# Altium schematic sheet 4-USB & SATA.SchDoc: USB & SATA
size B; CompanyName: NGRF; Address1: 2130 Howard Drive W; Address2: North Mankato, MN 56003; Address3: www.nextgenrf.com; Revision: 2; SheetNumber: 4; SheetTotal: 7; ProjName: BytePipe X9002_HDK
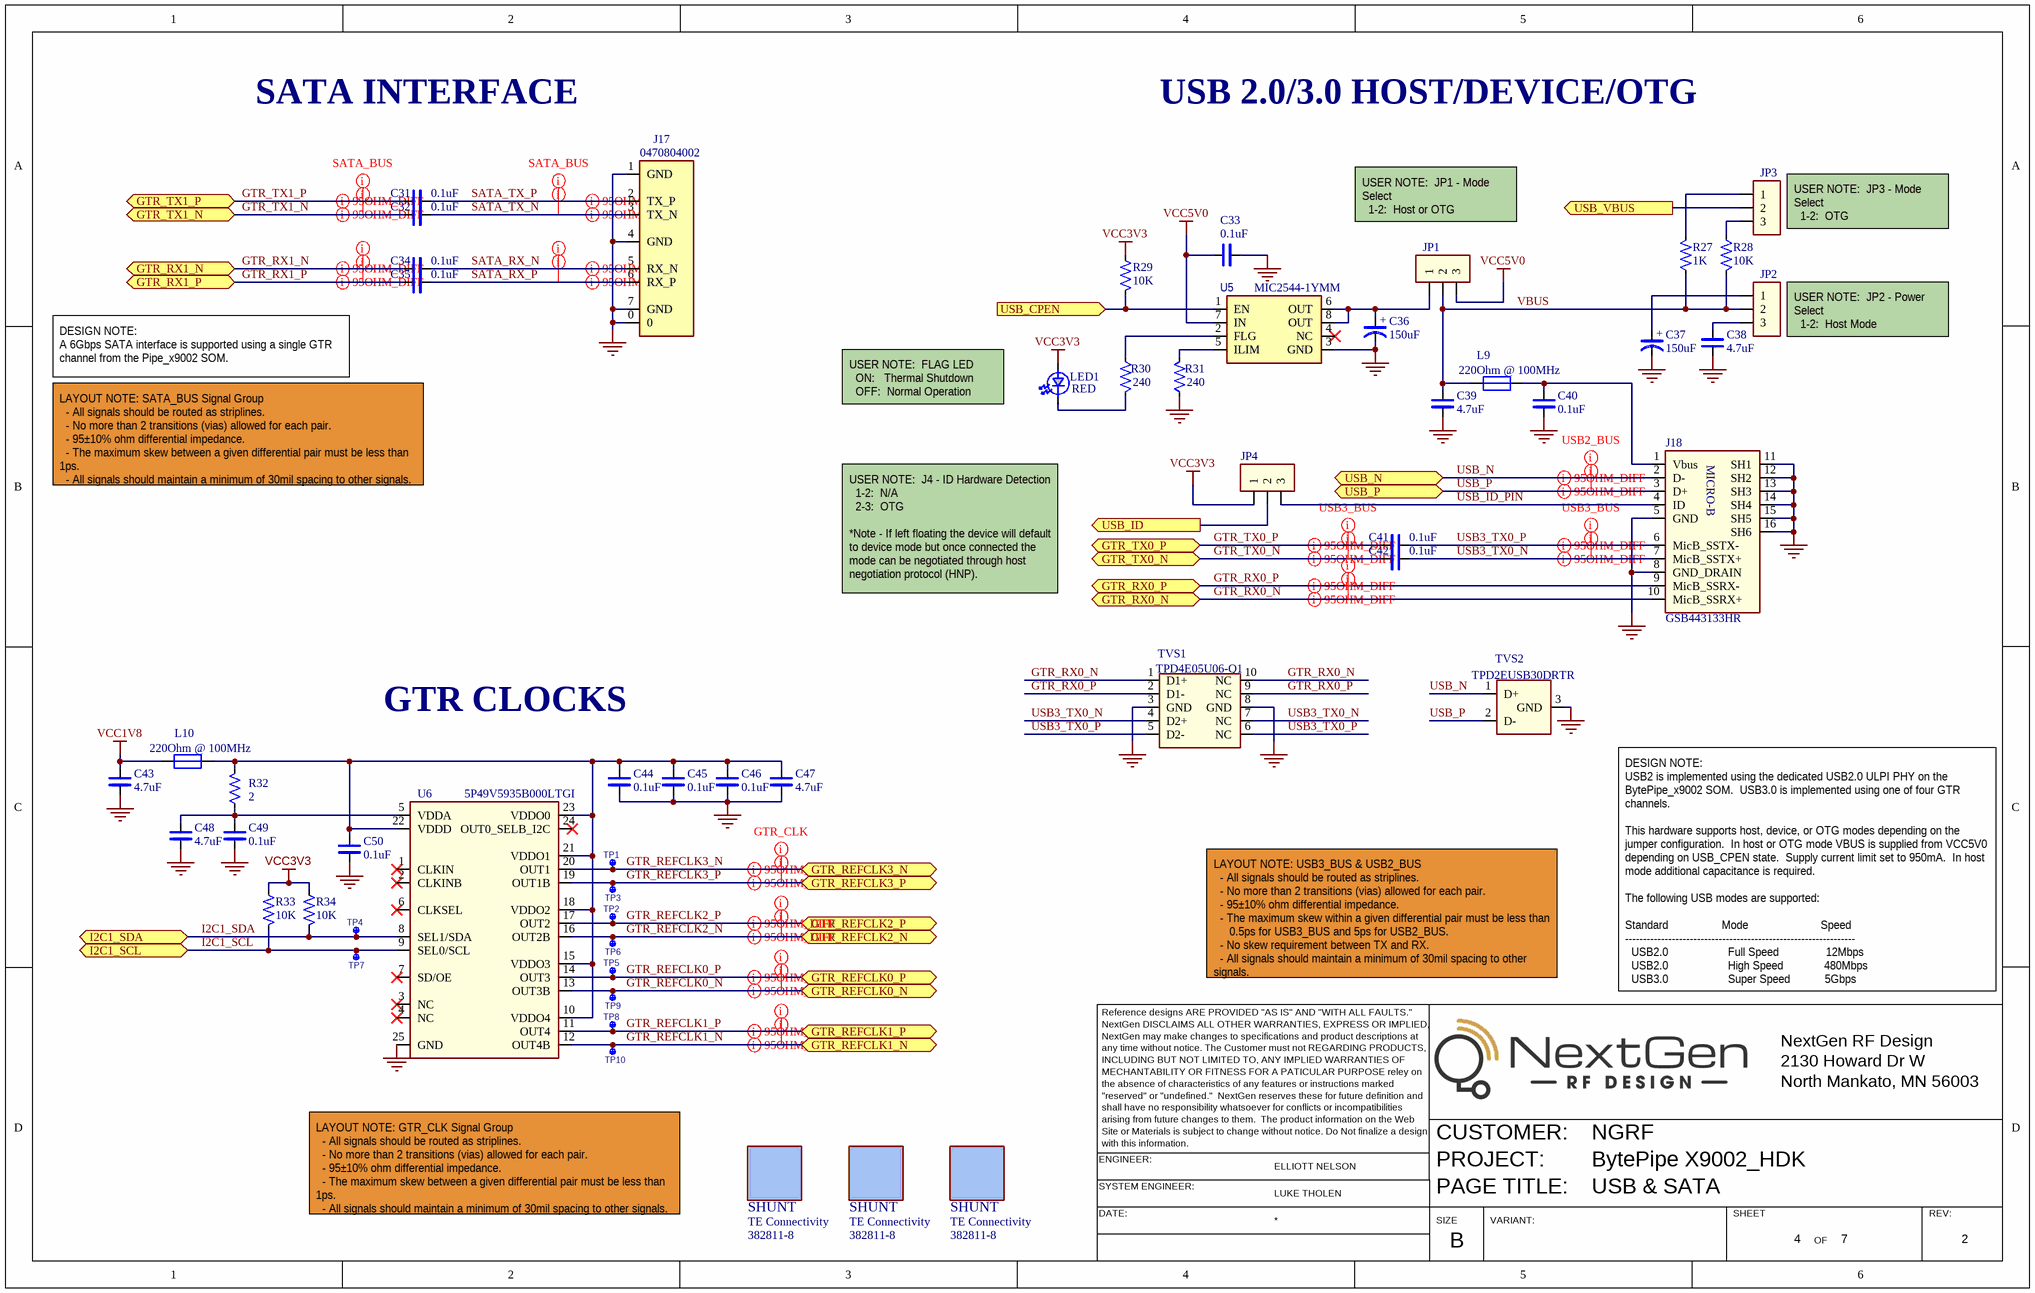
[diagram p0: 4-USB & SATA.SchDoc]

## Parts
C31  value 0.1uF  [SM/0402/CAP]  (hidden comment: CAP_CERAMIC_0402)
C32  value 0.1uF  [SM/0402/CAP]  (hidden comment: CAP_CERAMIC_0402)
C33  value 0.1uF  [SM/0402/CAP]  (hidden comment: CAP_CERAMIC_0402)
C34  value 0.1uF  [SM/0402/CAP]  (hidden comment: CAP_CERAMIC_0402)
C35  value 0.1uF  [SM/0402/CAP]  (hidden comment: CAP_CERAMIC_0402)
C36  value 150uF  [SM/CAP/TANT-D_A]  (hidden comment: TANT-D)
C37  value 150uF  [SM/CAP/TANT-D_A]  (hidden comment: TANT-D)
C38  value 4.7uF  [SM/0402/CAP]  (hidden comment: CAP_CERAMIC_0402)
C39  value 4.7uF  [SM/0402/CAP]  (hidden comment: CAP_CERAMIC_0402)
C40  value 0.1uF  [SM/0402/CAP]  (hidden comment: CAP_CERAMIC_0402)
C41  value 0.1uF  [SM/0402/CAP]  (hidden comment: CAP_CERAMIC_0402)
C42  value 0.1uF  [SM/0402/CAP]  (hidden comment: CAP_CERAMIC_0402)
C43  value 4.7uF  [SM/0402/CAP]  (hidden comment: CAP_CERAMIC_0402)
C44  value 0.1uF  [SM/0402/CAP]  (hidden comment: CAP_CERAMIC_0402)
C45  value 0.1uF  [SM/0402/CAP]  (hidden comment: CAP_CERAMIC_0402)
C46  value 0.1uF  [SM/0402/CAP]  (hidden comment: CAP_CERAMIC_0402)
C47  value 4.7uF  [SM/0402/CAP]  (hidden comment: CAP_CERAMIC_0402)
C48  value 4.7uF  [SM/0402/CAP]  (hidden comment: CAP_CERAMIC_0402)
C49  value 0.1uF  [SM/0402/CAP]  (hidden comment: CAP_CERAMIC_0402)
C50  value 0.1uF  [SM/0402/CAP]  (hidden comment: CAP_CERAMIC_0402)
J17  value 0470804002  [SM/CON/MLX/SATA/0470804002]  (hidden comment: CON_MOLEX_0470804002)
J18  value GSB443133HR  [SM/CON/USB3.1/MICRO B]  (hidden comment: CON_USB_3.1_MICRO-B_RA)
JP1  CON_100SP_1X3P_038H  [CON/100SP/1X3P]  (value not drawn)
JP2  CON_100SP_1X3P_038H  [CON/100SP/1X3P]  (value not drawn)
JP3  CON_100SP_1X3P_038H  [CON/100SP/1X3P]  (value not drawn)
JP4  CON_100SP_1X3P_038H  [CON/100SP/1X3P]  (value not drawn)
L9  value 220Ohm @ 100MHz  [SM/0603]  (hidden comment: FERRITE_0603_A)
L10  value 220Ohm @ 100MHz  [SM/0603]  (hidden comment: FERRITE_0603_A)
LED1  value RED  [SM/LED_0603]  (hidden comment: LED_0603)
R27  value 1K  [SM/0402/RES]  (hidden comment: RES_0402_A)
R28  value 10K  [SM/0402/RES]  (hidden comment: RES_0402_A)
R29  value 10K  [SM/0402/RES]  (hidden comment: RES_0402_A)
R30  value 240  [SM/0402/RES]  (hidden comment: RES_0402_A)
R31  value 240  [SM/0402/RES]  (hidden comment: RES_0402_A)
R32  value 2  [SM/0402/RES]  (hidden comment: RES_0402_A)
R33  value 10K  [SM/0402/RES]  (hidden comment: RES_0402_A)
R34  value 10K  [SM/0402/RES]  (hidden comment: RES_0402_A)
S1  SHUNT  OEM NAME: TE Connectivity  OEM#: 382811-8
S2  SHUNT  OEM NAME: TE Connectivity  OEM#: 382811-8
S3  SHUNT  OEM NAME: TE Connectivity  OEM#: 382811-8
TP1  TESTPOINT_030  [SM/TESTPOINT/30MIL]  (value not drawn)  (no BOM)
TP2  TESTPOINT_030  [SM/TESTPOINT/30MIL]  (value not drawn)  (no BOM)
TP3  TESTPOINT_030  [SM/TESTPOINT/30MIL]  (value not drawn)  (no BOM)
TP4  TESTPOINT_030  [SM/TESTPOINT/30MIL]  (value not drawn)  (no BOM)
TP5  TESTPOINT_030  [SM/TESTPOINT/30MIL]  (value not drawn)  (no BOM)
TP6  TESTPOINT_030  [SM/TESTPOINT/30MIL]  (value not drawn)  (no BOM)
TP7  TESTPOINT_030  [SM/TESTPOINT/30MIL]  (value not drawn)  (no BOM)
TP8  TESTPOINT_030  [SM/TESTPOINT/30MIL]  (value not drawn)  (no BOM)
TP9  TESTPOINT_030  [SM/TESTPOINT/30MIL]  (value not drawn)  (no BOM)
TP10  TESTPOINT_030  [SM/TESTPOINT/30MIL]  (value not drawn)  (no BOM)
TVS1  value TPD4E05U06-Q1  [SM/DFN10/2.5X1MM_A]  (hidden comment: TVS_TPD4E05U06_2.5mmX1mm)
TVS2  value TPD2EUSB30DRTR  [SM/SOT3_A]  (hidden comment: TVS_TPD2EUSB30DRTR_SOT3)
U5  value MIC2544-1YMM  [SM/MSOP8_A]  (hidden comment: IC_MIC2544-1YMM_MSOP-8)
U6  value 5P49V5935B000LTGI  [SM/LGA24/4X4/0.5LS_A]  (hidden comment: IC_5P49V5935_LGA-24)

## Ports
GTR_REFCLK0_N (bidir), GTR_REFCLK0_P (bidir), GTR_REFCLK1_N (bidir), GTR_REFCLK1_P (bidir), GTR_REFCLK2_N (bidir), GTR_REFCLK2_P (bidir), GTR_REFCLK3_N (bidir), GTR_REFCLK3_P (bidir), GTR_RX0_N (bidir), GTR_RX0_P (bidir), GTR_RX1_N (bidir), GTR_RX1_P (bidir), GTR_TX0_N (bidir), GTR_TX0_P (bidir), GTR_TX1_N (bidir), GTR_TX1_P (bidir), I2C1_SCL (bidir), I2C1_SDA (bidir), USB_CPEN (in), USB_ID (out), USB_N (bidir), USB_P (bidir), USB_VBUS (out)

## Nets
GND: C33.2(N2) C36.2(N) C37.2(N) C38.2(N2) C39.2(N2) C40.2(N2) C43.2(N2) C44.2(N2) C45.2(N2) C46.2(N2) C47.2(N2) C48.2(N2) C49.2(N2) C50.2(N2) J17.0 J17.1(GND) J17.4(GND) J17.7(GND) J18.5(GND) J18.8(GND_DRAIN) J18.11(SH1) J18.12(SH2) J18.13(SH3) J18.14(SH4) J18.15(SH5) J18.16(SH6) R31.2 TVS1.3(GND) TVS1.8(GND) TVS2.3(GND) U5.3(GND) U6.25(GND)
VCC1V8: C43.1(N1) L10.1(PIN1)
VCC3V3: JP4.1 LED1.2(A) R29.1 R33.1 R34.1
VCC5V0: C33.1(N1) JP1.3 U5.7(IN)
GTR_REFCLK0_N: TP9.1(N1) U6.13(OUT3B) ; port GTR_REFCLK0_N
GTR_REFCLK0_P: TP5.1(N1) U6.14(OUT3) ; port GTR_REFCLK0_P
GTR_REFCLK1_N: TP10.1(N1) U6.12(OUT4B) ; port GTR_REFCLK1_N
GTR_REFCLK1_P: TP8.1(N1) U6.11(OUT4) ; port GTR_REFCLK1_P
GTR_REFCLK2_N: TP6.1(N1) U6.16(OUT2B) ; port GTR_REFCLK2_N
GTR_REFCLK2_P: TP2.1(N1) U6.17(OUT2) ; port GTR_REFCLK2_P
GTR_REFCLK3_N: TP1.1(N1) U6.20(OUT1) ; port GTR_REFCLK3_N
GTR_REFCLK3_P: TP3.1(N1) U6.19(OUT1B) ; port GTR_REFCLK3_P
GTR_RX0_N: J18.10(MicB_SSRX+) TVS1.1(D1+) TVS1.10(NC) ; port GTR_RX0_N
GTR_RX0_P: J18.9(MicB_SSRX-) TVS1.2(D1-) TVS1.9(NC) ; port GTR_RX0_P
GTR_RX1_N: C34.1(N1) ; port GTR_RX1_N
GTR_RX1_P: C35.1(N1) ; port GTR_RX1_P
GTR_TX0_N: C42.1(N1) ; port GTR_TX0_N
GTR_TX0_P: C41.1(N1) ; port GTR_TX0_P
GTR_TX1_N: C32.1(N1) ; port GTR_TX1_N
GTR_TX1_P: C31.1(N1) ; port GTR_TX1_P
I2C1_SCL: R33.2 TP7.1(N1) U6.9(SEL0/SCL) ; port I2C1_SCL
I2C1_SDA: R34.2 TP4.1(N1) U6.8(SEL1/SDA) ; port I2C1_SDA
SATA_RX_N: C34.2(N2) J17.5(RX_N)
SATA_RX_P: C35.2(N2) J17.6(RX_P)
SATA_TX_N: C32.2(N2) J17.3(TX_N)
SATA_TX_P: C31.2(N2) J17.2(TX_P)
USB3_TX0_N: C42.2(N2) J18.7(MicB_SSTX+) TVS1.4(D2+) TVS1.7(NC)
USB3_TX0_P: C41.2(N2) J18.6(MicB_SSTX-) TVS1.5(D2-) TVS1.6(NC)
USB_CPEN: R29.2 U5.1(EN) ; port USB_CPEN
USB_ID: JP4.2 ; port USB_ID
USB_ID_PIN: J18.4(ID) JP4.3
USB_N: J18.2(D-) TVS2.1(D+) ; port USB_N
USB_P: J18.3(D+) TVS2.2(D-) ; port USB_P
USB_VBUS: JP3.2 ; port USB_VBUS
VBUS: C39.1(N1) JP1.2 JP2.2 L9.1(PIN1) R27.1 R28.2
NetC36_1: C36.1(+) JP1.1 U5.6(OUT) U5.8(OUT)
NetC37_1: C37.1(+) JP2.1
NetC38_1: C38.1(N1) JP2.3
NetC40_1: C40.1(N1) J18.1(Vbus) L9.2(PIN2)
NetC44_1: C44.1(N1) C45.1(N1) C46.1(N1) C47.1(N1) C50.1(N1) L10.2(PIN2) R32.1 U6.10(VDDO4) U6.15(VDDO3) U6.18(VDDO2) U6.21(VDDO1) U6.22(VDDD) U6.23(VDDO0)
NetC48_1: C48.1(N1) C49.1(N1) R32.2 U6.5(VDDA)
NetJP3_1: JP3.1 R27.2
NetJP3_3: JP3.3 R28.1
NetLED1_1: LED1.1(C) R30.1
NetR30_2: R30.2 U5.2(FLG)
NetR31_1: R31.1 U5.5(ILIM)

Not connected (* = marked no-connect by the designer): U5 4(NC)*; U6 1(CLKIN)* 2(CLKINB)* 3(NC)* 4(NC)* 6(CLKSEL)* 7(SD/OE)* 24(OUT0_SELB_I2C)*

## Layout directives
net class USB3_BUS: GTR_RX0_N, GTR_RX0_P, GTR_TX0_N, GTR_TX0_P, USB3_TX0_N, USB3_TX0_P
net class USB2_BUS: USB_N, USB_P
differential pair; Impedance: 90 Ohms; differential pair class 95OHM_DIFF: GTR_REFCLK0_N, GTR_REFCLK0_P, GTR_REFCLK1_N, GTR_REFCLK1_P, GTR_REFCLK2_N, GTR_REFCLK2_P, GTR_REFCLK3_N, GTR_REFCLK3_P, GTR_RX0_N, GTR_RX0_P, GTR_RX1_N, GTR_RX1_P, GTR_TX0_N, GTR_TX0_P, GTR_TX1_N, GTR_TX1_P, SATA_RX_N, SATA_RX_P, SATA_TX_N, SATA_TX_P, USB3_TX0_N, USB3_TX0_P, USB_N, USB_P
net class SATA_BUS: GTR_RX1_N, GTR_RX1_P, GTR_TX1_N, GTR_TX1_P, SATA_RX_N, SATA_RX_P, SATA_TX_N, SATA_TX_P
net class GTR_CLK: GTR_REFCLK0_N, GTR_REFCLK0_P, GTR_REFCLK1_N, GTR_REFCLK1_P, GTR_REFCLK2_N, GTR_REFCLK2_P, GTR_REFCLK3_N, GTR_REFCLK3_P

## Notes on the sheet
- SATA INTERFACE
- USB 2.0/3.0 HOST/DEVICE/OTG
- USER NOTE:  JP1 - Mode Select
  1-2:  Host or OTG
  2-3:  Device
- (near JP3) USER NOTE:  JP3 - Mode Select
  1-2:  OTG
  2-3:  Device or Host
- DESIGN NOTE:
  A 6Gbps SATA interface is supported using a single GTR channel from the Pipe_x9002 SOM.
- (near JP2) USER NOTE:  JP2 - Power Select
  1-2:  Host Mode
  2-3:  Device or OTG
- USER NOTE:  FLAG LED
  ON:   Thermal Shutdown
  OFF:  Normal Operation
- LAYOUT NOTE: SATA_BUS Signal Group
  - All signals should be routed as striplines.
  - No more than 2 transitions (vias) allowed for each pair.
  - 95±10% ohm differential impedance.
  - The maximum skew between a given differential pair must be less than 1ps.
  - All signals should maintain a minimum of 30mil spacing to other signals.
- USER NOTE:  J4 - ID Hardware Detection
  1-2:  N/A
  2-3:  OTG
  *Note - If left floating the device will default to device mode but once connected the mode can be negotiated through host negotiation protocol (HNP).
- GTR CLOCKS
- LAYOUT NOTE: USB3_BUS & USB2_BUS
  - All signals should be routed as striplines.
  - No more than 2 transitions (vias) allowed for each pair.
  - 95±10% ohm differential impedance.
  - The maximum skew within a given differential pair must be less than
  0.5ps for USB3_BUS and 5ps for USB2_BUS.
  - No skew requirement between TX and RX.
  - All signals should maintain a minimum of 30mil spacing to other signals.
- Reference designs ARE PROVIDED "AS IS" AND "WITH ALL FAULTS."
- NextGen DISCLAIMS ALL OTHER WARRANTIES, EXPRESS OR IMPLIED,
- NextGen may make changes to specifications and product descriptions at
- DESIGN NOTE:
  USB2 is implemented using the dedicated USB2.0 ULPI PHY on the BytePipe_x9002 SOM.  USB3.0 is implemented using one of four GTR channels.
  This hardware supports host, device, or OTG modes depending on the jumper configuration.  In host or OTG mode VBUS is supplied from VCC5V0 depending on USB_CPEN state.  Supply current limit set to 950mA.  In host mode additional capacitance is required.
  The following USB modes are supported:
  Standard                 Mode                       Speed
  ----------------------------------------------------------------
  USB2.0                   Full Speed               12Mbps
  USB2.0                   High Speed             480Mbps
  USB3.0                   Super Speed           5Gbps
- NextGen RF Design
- any time without notice. The Customer must not REGARDING PRODUCTS,
- INCLUDING BUT NOT LIMITED TO, ANY IMPLIED WARRANTIES OF
- MECHANTABILITY OR FITNESS FOR A PATICULAR PURPOSE reley on
- "reserved" or "undefined."  NextGen reserves these for future definition and
- the absence of characteristics of any features or instructions marked
- shall have no responsibility whatsoever for conflicts or incompatibilities
- 2130 Howard Dr W
- North Mankato, MN 56003
- ENGINEER:
- Site or Materials is subject to change without notice. Do Not finalize a design
- with this information.
- arising from future changes to them.  The product information on the Web
- ELLIOTT NELSON
- CUSTOMER:
- PROJECT:
- LAYOUT NOTE: GTR_CLK Signal Group
  - All signals should be routed as striplines.
  - No more than 2 transitions (vias) allowed for each pair.
  - 95±10% ohm differential impedance.
  - The maximum skew between a given differential pair must be less than 1ps.
  - All signals should maintain a minimum of 30mil spacing to other signals.
- SYSTEM ENGINEER:
- DATE:
- LUKE THOLEN
- SIZE
- PAGE TITLE:
- VARIANT:
- SHEET
- OF
- REV:
- B

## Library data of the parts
C31-C35 C40-C42 C44-C46 C49 C50 = CAP_CERAMIC_0402: CAP CER 0.1UF 25V X7R 0402; TOL: ±10%; OEM#: CL05B104KA5NNNC; OEM NAME: Samsung
C36 C37 = CAP_TANT-D: CAP TANT 150UF 20% 10V 2917; OEM#: T491D157M010AT; OEM NAME: KEMET
C38 C39 C43 C47 C48 = CAP_CERAMIC_0402: CAP CER 4.7UF 10V X5R 0402; TOL: ±20%; OEM#: CL05A475MP5NRNC; OEM NAME: Samsung
J17 = CON_MOLEX_0470804002: 7 Position SATA Plug Connector Solder Surface Mount, Right Angle; OEM NAME: MOLEX
J18 = CON_USB_3.1_MICRO-B_RA: CONN RCPT USB3.1 MICRO B SMD R/A; OEM NAME: Amphenol ICC
JP1-JP4 = CON_100SP_1X3P_038H: PIN HEADER, SINGLE ROW 3 PIN STR; OEM#: PH1-03-UA; OEM NAME: Adam Tech; VALUE: PH1-03-UA
L9 L10 = FERRITE_0603_A: 120 Ohms @ 100MHz 1 Power Line Ferrite Bead 0603 (1608 Metric) 3A 25mOhm; OEM#: BLM18SG121TN1D; OEM NAME: Murata Electronics
LED1 = LED_0603: LED-0603; OEM#: LS Q976-NR-1; OEM NAME: OSRAM
R27 = RES_0402_A: RES SMD 1K OHM 1% 1/10W 0402; OEM#: ERJ-2RKF1001X; OEM NAME: Panasonic
R28 R29 R33 R34 = RES_0402_A: OEM#: ERJ-2RKF1002X; OEM NAME: Panasonic; TOL: ±1%
R30 R31 = RES_0402_A: RES SMD 240 OHM 1% 1/10W 0402; OEM#: ERJ-2RKF2400X; OEM NAME: Panasonic
R32 = RES_0402_A: RES 2 OHM 1% 1/10W 0402 SMD; OEM#: ERJ-U02F2R00X; OEM NAME: Panasonic
S1-S3 = BOM_COMPONENT_NO-FOOTPRINT
TVS1 = TVS_TPD4E05U06_2.5mmX1mm: TVS DIODE 5.5V 14V 10SON; OEM NAME: TI
TVS2 = TVS_TPD2EUSB30DRTR_SOT3: TVS DIODE 5.5V 8V SOT3; OEM NAME: Texas Instruments; WATT: 45
U5 = IC_MIC2544-1YMM_MSOP-8: Power Switch/Driver 1:1 N-Channel 1.5A 8-MSOP; OEM NAME: MICROCHIP
U6 = IC_5P49V5935_LGA-24: IC Programable Clock Generator; OEM NAME: Renesas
